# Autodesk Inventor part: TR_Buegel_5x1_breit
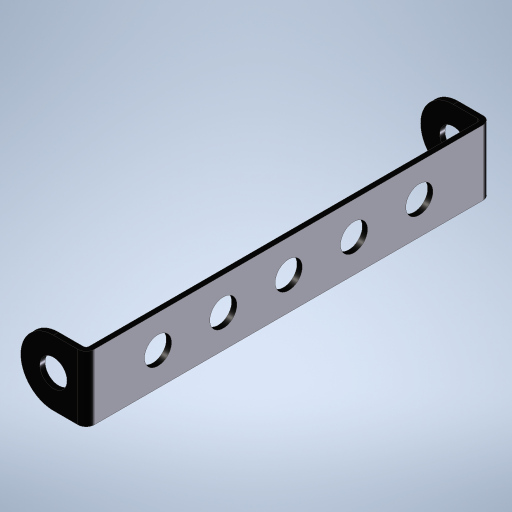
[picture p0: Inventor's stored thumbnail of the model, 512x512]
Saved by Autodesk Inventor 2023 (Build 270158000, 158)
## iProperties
Created: 2023-11
Part Number: TR_Buegel_5x1_breit
Material: Edelstahl
Document SubType Name: Modeling
Designer: Admin
Density: 8 g/cm^3
Appearance: Halbpoliert
Author: Admin
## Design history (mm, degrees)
sketch "Skizze1"
  geometry: L1 (10, 31)-(1.25, 31); L2 (0, 29.75)-(0, -29.75); L3 (1.25, -31)-(10, -31); L4 (10, -31)-(10, -30.2); L5 (10, -30.2)-(1.25, -30.2); L6 (0.8, -29.75)-(0.8, 29.75); L7 (1.25, 30.2)-(10, 30.2); L8 (10, 30.2)-(10, 31); A1 r 1.25 centre (1.25, 29.75) between (1.25, 31) and (0, 29.75); A2 r 1.25 centre (1.25, -29.75) between (0, -29.75) and (1.25, -31); A3 r 0.45 centre (1.25, 29.75) between (1.25, 30.2) and (0.8, 29.75); A4 r 0.45 centre (1.25, -29.75) between (0.8, -29.75) and (1.25, -30.2); 5 further points
  constraints: 16 end point, 8 point on circle, 8 tangent, 4 centre point, 4 point on line, 3 horizontal, 3 perpendicular, 2 equal radius, 2 midpoint, 2 vertical alignment, 1 coincident, 1 collinear, 1 horizontal alignment, 1 parallel, 1 vertical
  dimensions: "d0" = 0.8 distance of L7.end L1.start (= Dicke); "d1" = 10 horizontal distance of point (0, 0) L1.start (= Einheitsmaß); "d2" = 0.8 horizontal distance of point (0, 0) point (0.8, 30.2) (= Dicke); "d6" = 1.25 radius of A1; "d7" = 62 distance of L3.end L1.start
extrude "Extrusion1" new body sketch "Skizze1" stored distance "d8" = 10 (= Einheitsmaß); taper "d9" = 0 deg
fillet "Rundung1" dims "d10" = 5 (= 0.5 x Einheitsmaß)
sketch "Skizze2"
  geometry: C1 r 2.075 at (-5, 0); A1 r 5 centre (-5, 0) between (-5, 5) and (-5, -5) reference; 1 further point
  constraints: 1 centre point, 1 coincident
  dimensions: "d11" = 4.15 diameter of C1 (= 2 x Radius)
extrude "Extrusion2" cut sketch "Skizze2" extent not by distance; stored distance "d12" = 0; taper "d13" = 0 deg
sketch "Skizze3"
  geometry: C1 r 2.075 at (0, 0); 1 further point
  constraints: 1 centre point, 1 coincident
  dimensions: "d14" = 4.15 diameter of C1 (= 2 x Radius)
extrude "Extrusion3" cut sketch "Skizze3" extent not by distance; stored distance "d15" = 0; taper "d16" = 0 deg
pattern_linear "Rechteckige Anordnung2" dims "d22" = 10 (= Einheitsmaß)
node "Volumenkörper1"
other parameters: "Einheitsmaß" = 10 [user parameter; used in 4 equation terms], "Radius" = 2.075 [user parameter; used in 2 equation terms], "Fasen" = 0.5 [user parameter], "Dicke" = 0.8 [user parameter; used in 2 equation terms]
